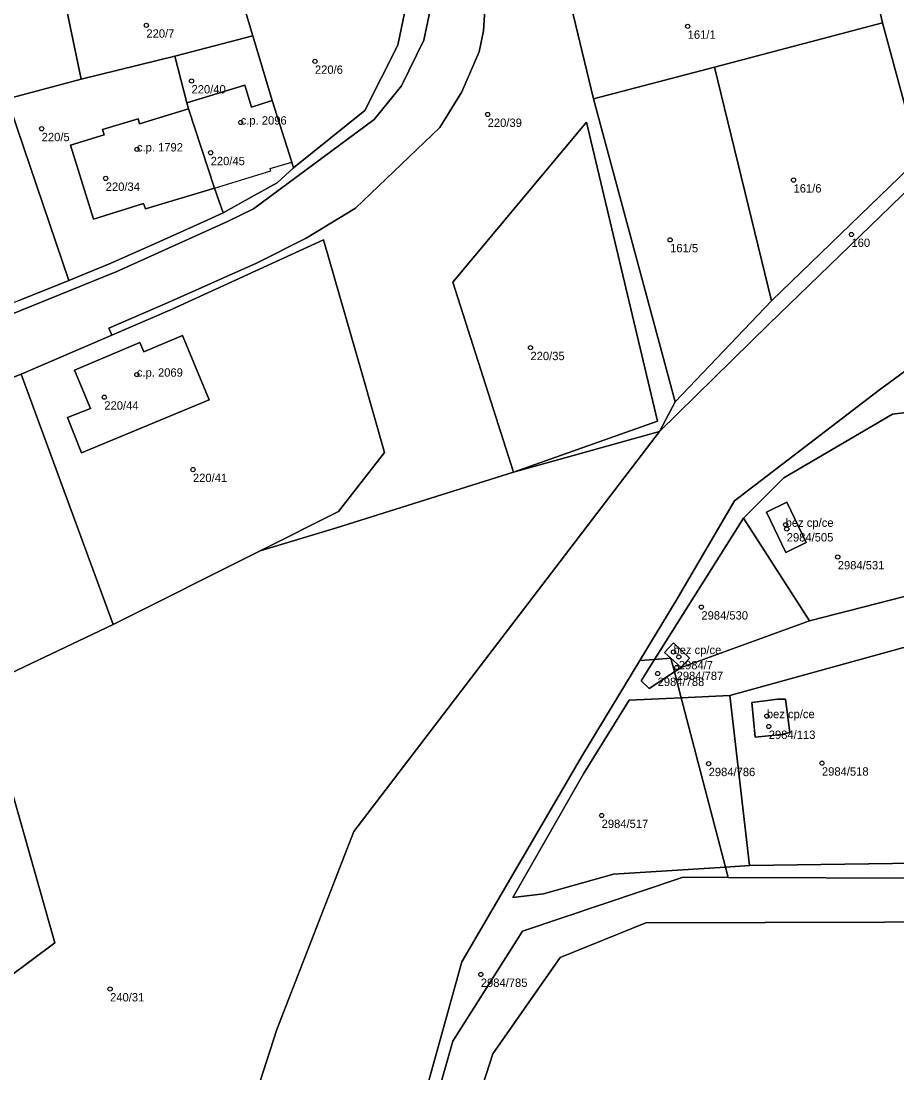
# Model space of a CAD drawing. Extents: x -878211 to -870363, y -1058464 to -1052522.
# Drawn here: x -874079.4 to -873974.6, y -1056112.5 to -1055986.6 of the extents above; entities that cross this region are included whole.
import ezdxf

# ---------------------------------------------------------------- set-up
doc = ezdxf.new("R2010")
doc.units = 0
for name, color, linetype in [('Definiční body', 7, 'Continuous'), ('Polygon budovy', 7, 'Continuous'), ('Polygon parcely', 7, 'Continuous')]:
    doc.layers.add(name, color=color, linetype=linetype)

msp = doc.modelspace()

# ---------------------------------------------------------------- linework, layer by layer
at = {"layer": 'Definiční body'}
for centre in [(-874064.38, -1055987.13994), (-873999.64, -1055987.26994), (-874044.22, -1055991.45994), (-874058.98, -1055993.80994), (-874023.56, -1055997.80994), (-874053.1, -1055998.76994), (-874076.9, -1055999.51994), (-874065.51, -1056001.98994), (-874056.69, -1056002.38994), (-874069.24, -1056005.45994), (-873986.98, -1056005.65994), (-874001.74, -1056012.80994), (-873980.05, -1056012.16994), (-874018.44, -1056025.70994), (-874065.52, -1056028.92994), (-874069.41, -1056031.62994), (-874058.81, -1056040.28994), (-873987.92, -1056046.88994), (-873987.79, -1056047.39994), (-873981.69, -1056050.73994), (-873998, -1056056.73994), (-874001.34, -1056062.10994), (-874000.7, -1056062.68994), (-874003.23, -1056064.68994), (-874000.96, -1056063.96994), (-873990.17, -1056069.77994), (-873989.94, -1056071.01994), (-873997.13, -1056075.46994), (-873983.58, -1056075.40994), (-874009.93, -1056081.66994), (-874024.38, -1056100.67994), (-874068.72, -1056102.41994)]:
    msp.add_circle(centre, 0.25, dxfattribs=at)
at = {"layer": 'Polygon budovy'}
for points in [[(-874052.61, -1055994.31), (-874059.55, -1055996.42), (-874059.34, -1055997.15), (-874056.25, -1056006.62), (-874049.48, -1056004.57), (-874049.57, -1056004.28), (-874046.98, -1056003.51), (-874049.34, -1055996.14), (-874051.81, -1055996.92)], [(-874069.42, -1056000.25), (-874073.45, -1056001.47), (-874070.69, -1056010.33), (-874064.71, -1056008.48), (-874064.5, -1056009.11), (-874056.25, -1056006.62), (-874059.34, -1055997.15), (-874065.19, -1055998.95), (-874065.37, -1055998.34), (-874069.63, -1055999.62)], [(-874073.8, -1056034.07), (-874072.12, -1056038.28), (-874056.85, -1056031.94), (-874060.06, -1056024.27), (-874064.69, -1056026.2), (-874065.16, -1056025.09), (-874072.97, -1056028.39), (-874071.06, -1056032.98)], [(-873990.21, -1056045.38), (-873987.9, -1056050.21), (-873985.45, -1056049.03), (-873987.79, -1056044.18)], [(-874001.33, -1056061.02), (-874002.41, -1056062.16), (-874001.64, -1056062.85), (-874000.43, -1056063.95), (-873999.41, -1056062.83)], [(-873988.84, -1056067.77), (-873991.98, -1056068.16), (-873991.56, -1056072.29), (-873988.36, -1056071.96), (-873987.41, -1056071.73), (-873987.92, -1056067.76)]]:
    msp.add_lwpolyline(points, close=True, dxfattribs=at)
at = {"layer": 'Polygon parcely'}
for points in [[(-873971.94, -1056003.04), (-873966.71, -1056000.36), (-873958.05, -1055994.81), (-873973.04, -1055933.04), (-873973.58, -1055928.96), (-873988.5, -1055932.46), (-873987.49, -1055942.14), (-873979.72, -1055972.17), (-873977.52, -1055981.57), (-873976.33, -1055986.86)], [(-874061.46, -1055955.78), (-874078.43, -1055966.08), (-874076.97, -1055970.76), (-874073.03, -1055969.93), (-874072.64, -1055971.8), (-874066.64, -1055970.52), (-874064.5, -1055980.27), (-874074.5, -1055982.46), (-874072.17, -1055993.59), (-874060.99, -1055990.85), (-874051.65, -1055988.42)], [(-874032.66, -1055981.61), (-874033.78, -1055973.82), (-874038.62, -1055964.71), (-874061.46, -1055955.78), (-874051.65, -1055988.42), (-874049.34, -1055996.14), (-874046.98, -1056003.51), (-874046.78, -1056004.18), (-874038.26, -1055997.34), (-874034.3, -1055989.51)], [(-874095.92, -1055972.47), (-874104.9, -1055975.23), (-874098.11, -1056000.54), (-874081, -1055995.96), (-874072.17, -1055993.59), (-874074.5, -1055982.46), (-874084.39, -1055984.6), (-874086.47, -1055974.86), (-874080.27, -1055973.53), (-874080.69, -1055971.59), (-874076.97, -1055970.76), (-874078.43, -1055966.08), (-874089.47, -1055971)], [(-874009.03, -1055966.11), (-874018.21, -1055965.65), (-874010.89, -1055995.93), (-873996.44, -1055992.14), (-873976.33, -1055986.86), (-873977.52, -1055981.57), (-873983.85, -1055983.05), (-873984.61, -1055984.28), (-873986.14, -1055984.64), (-873987.49, -1055983.84), (-873987.84, -1055982.3), (-873987.07, -1055981.06), (-873988.65, -1055974.24), (-874005.5, -1055979.01)], [(-873971.94, -1056003.04), (-873976.33, -1055986.86), (-873996.44, -1055992.14), (-873989.6, -1056020.11)], [(-874059.55, -1055996.42), (-874052.61, -1055994.31), (-874051.81, -1055996.92), (-874049.34, -1055996.14), (-874051.65, -1055988.42), (-874060.99, -1055990.85)], [(-874070.69, -1056010.33), (-874073.45, -1056001.47), (-874069.42, -1056000.25), (-874069.63, -1055999.62), (-874065.37, -1055998.34), (-874065.19, -1055998.95), (-874059.34, -1055997.15), (-874059.55, -1055996.42), (-874060.99, -1055990.85), (-874072.17, -1055993.59), (-874081, -1055995.96), (-874079.82, -1055999.45), (-874073.66, -1056017.67), (-874068.71, -1056015.62), (-874063.13, -1056013.18), (-874057.09, -1056010.44), (-874055.18, -1056009.57), (-874056.25, -1056006.62), (-874064.5, -1056009.11), (-874064.71, -1056008.48)], [(-873996.44, -1055992.14), (-874010.89, -1055995.93), (-874001.15, -1056032.18), (-873989.6, -1056020.11)], [(-874046.78, -1056004.18), (-874046.98, -1056003.51), (-874049.34, -1055996.14), (-874051.81, -1055996.92), (-874052.61, -1055994.31), (-874059.55, -1055996.42), (-874059.34, -1055997.15), (-874056.25, -1056006.62), (-874055.18, -1056009.57), (-874051.48, -1056007.49), (-874048.75, -1056006)], [(-874079.82, -1055999.45), (-874081, -1055995.96), (-874098.11, -1056000.54), (-874104.71, -1056002.08), (-874096.92, -1056026.27), (-874079.52, -1056020.04), (-874073.66, -1056017.67)], [(-874059.34, -1055997.15), (-874065.19, -1055998.95), (-874065.37, -1055998.34), (-874069.63, -1055999.62), (-874069.42, -1056000.25), (-874073.45, -1056001.47), (-874070.69, -1056010.33), (-874064.71, -1056008.48), (-874064.5, -1056009.11), (-874056.25, -1056006.62)], [(-874003.26, -1056034.48), (-874011.74, -1055998.72), (-874027.74, -1056017.87), (-874020.49, -1056040.6)], [(-874003.26, -1056034.48), (-874020.49, -1056040.6), (-874027.74, -1056017.87), (-874011.74, -1055998.72)], [(-873975.38, -1056008.83), (-873966.71, -1056000.36), (-873971.94, -1056003.04), (-873989.6, -1056020.11), (-874001.15, -1056032.18), (-874003.01, -1056035.73), (-873989.92, -1056022.91)], [(-874068.51, -1056024.22), (-874079.34, -1056028.88), (-874068.35, -1056058.84), (-874050.77, -1056050.02), (-874041.39, -1056045.32), (-874035.88, -1056038.23), (-874038.62, -1056028.71), (-874043.19, -1056012.81), (-874061.28, -1056021.1)], [(-874064.69, -1056026.2), (-874065.16, -1056025.09), (-874072.97, -1056028.39), (-874071.06, -1056032.98), (-874073.8, -1056034.07), (-874072.12, -1056038.28), (-874056.85, -1056031.94), (-874060.06, -1056024.27)], [(-874064.69, -1056026.2), (-874060.06, -1056024.27), (-874056.85, -1056031.94), (-874072.12, -1056038.28), (-874073.8, -1056034.07), (-874071.06, -1056032.98), (-874072.97, -1056028.39), (-874065.16, -1056025.09)], [(-874101.01, -1056036.26), (-874089.71, -1056068.99), (-874083.99, -1056066.24), (-874068.35, -1056058.84), (-874079.34, -1056028.88), (-874082.74, -1056030.19), (-874093.51, -1056033.97)], [(-873985.07, -1056058.37), (-873967.5, -1056053.87), (-873971.22, -1056033.18), (-873975.13, -1056033.66), (-873988.15, -1056041.27), (-873992.97, -1056046.1)], [(-874083.99, -1056066.24), (-874080.7, -1056077.88), (-874075.33, -1056096.89), (-874092.05, -1056109.34), (-874118.47, -1056117.14), (-874116.81, -1056122.76), (-874101.89, -1056134.11), (-874098.83, -1056136.48), (-874062.01, -1056135.86), (-874057.99, -1056135.83), (-874048.77, -1056107.25), (-874039.57, -1056083.57), (-874003.01, -1056035.73), (-874020.49, -1056040.6), (-874041.66, -1056047.24), (-874050.77, -1056050.02), (-874068.35, -1056058.84)], [(-873987.79, -1056044.18), (-873990.21, -1056045.38), (-873987.9, -1056050.21), (-873985.45, -1056049.03)], [(-873987.79, -1056044.18), (-873985.45, -1056049.03), (-873987.9, -1056050.21), (-873990.21, -1056045.38)], [(-874003.6, -1056063), (-874001.64, -1056062.85), (-874002.41, -1056062.16), (-874001.33, -1056061.02), (-873999.41, -1056062.83), (-874000.43, -1056063.95), (-873985.07, -1056058.37), (-873992.97, -1056046.1)], [(-873999.41, -1056062.83), (-874001.33, -1056061.02), (-874002.41, -1056062.16), (-874001.64, -1056062.85), (-874000.43, -1056063.95)], [(-873992.23, -1056087.66), (-873966.56, -1056087.27), (-873968.55, -1056073.84), (-873970.91, -1056060.77), (-873994.59, -1056067.33)], [(-874012.08, -1056076.67), (-874006.62, -1056067.86), (-874000.4, -1056067.59), (-874001.22, -1056064.47), (-874004.25, -1056066.47), (-874005.21, -1056065.57), (-874003.6, -1056063), (-874005.36, -1056063.14), (-874012.21, -1056074.45), (-874026.65, -1056099.18), (-874033.12, -1056122.42), (-874035.94, -1056133.05), (-874034.52, -1056132.5), (-874027.71, -1056108.65), (-874019.41, -1056095.51), (-874000.16, -1056089.06), (-873994.8, -1056089.08), (-873995.12, -1056087.84), (-874008.5, -1056088.69), (-874016.88, -1056091.03), (-874020.55, -1056091.49)], [(-874001.22, -1056064.47), (-874001.64, -1056062.85), (-874003.6, -1056063), (-874005.21, -1056065.57), (-874004.25, -1056066.47)], [(-874001.22, -1056064.47), (-874000.43, -1056063.95), (-874001.64, -1056062.85)], [(-874000.4, -1056067.59), (-874006.62, -1056067.86), (-874012.08, -1056076.67), (-874020.55, -1056091.49), (-874016.88, -1056091.03), (-874008.5, -1056088.69), (-873995.12, -1056087.84)], [(-873992.23, -1056087.66), (-873994.59, -1056067.33), (-874000.4, -1056067.59), (-873995.12, -1056087.84)], [(-873988.36, -1056071.96), (-873987.41, -1056071.73), (-873987.92, -1056067.76), (-873988.84, -1056067.77), (-873991.98, -1056068.16), (-873991.56, -1056072.29)], [(-873988.36, -1056071.96), (-873991.56, -1056072.29), (-873991.98, -1056068.16), (-873988.84, -1056067.77), (-873987.92, -1056067.76), (-873987.41, -1056071.73)], [(-873994.8, -1056089.08), (-873878.08, -1056089.5), (-873840.34, -1056089.55), (-873842.5, -1056082.5), (-873863.42, -1056084.29), (-873881.47, -1056084.35), (-873904.02, -1056084.6), (-873904.11, -1056084.01), (-873924.77, -1056085.52), (-873949.6, -1056086.44), (-873966.56, -1056087.27), (-873992.23, -1056087.66), (-873995.12, -1056087.84)], [(-873965.35, -1056164.18), (-873947.09, -1056155), (-873961.82, -1056094.39), (-874004.66, -1056094.51), (-874014.9, -1056098.66), (-874022.95, -1056110.18), (-874027.4, -1056124.02), (-874040.47, -1056163.31), (-874041.38, -1056163.05), (-874042.62, -1056175.62), (-874041.72, -1056201.74), (-874038.77, -1056221.03), (-874035.3, -1056231.92), (-874016.67, -1056231.12), (-873971.13, -1056232.61), (-873962.33, -1056230.05)]]:
    msp.add_lwpolyline(points, close=True, dxfattribs=at)
for points in [[(-874082.74, -1056030.19), (-874079.34, -1056028.88), (-874068.51, -1056024.22), (-874068.87, -1056023.39), (-874061.78, -1056020.31), (-874051.21, -1056015.58), (-874045.28, -1056012.6), (-874039.36, -1056009.01), (-874029.28, -1055999.36), (-874026.64, -1055995.1), (-874024.59, -1055990.32), (-874024.07, -1055987.79), (-874023.46, -1055978.22), (-874024.41, -1055972.01), (-874026.04, -1055967.55), (-874027.4, -1055965.3), (-874028.36, -1055963.96), (-874031.92, -1055959.69), (-874036.44, -1055955.98), (-874044.57, -1055950.98), (-874047.99, -1055949.47), (-874050.57, -1055948.5), (-874079.9, -1055941.21)], [(-874086.33, -1056024.06), (-874067.92, -1056016.59), (-874054.77, -1056010.67), (-874051.56, -1056009.11), (-874037.13, -1055998.43), (-874033.88, -1055994.4), (-874031.19, -1055988.93), (-874029.78, -1055982.07), (-874030.25, -1055974.01), (-874031.69, -1055968.99), (-874036.22, -1055963.17), (-874039.26, -1055960.99), (-874053.99, -1055954.45), (-874058.59, -1055953.79), (-874062.33, -1055954.49), (-874091.53, -1055969.3)], [(-874091.53, -1055969.3), (-874062.33, -1055954.49), (-874058.59, -1055953.79), (-874053.99, -1055954.45), (-874039.26, -1055960.99), (-874036.22, -1055963.17), (-874031.69, -1055968.99), (-874030.25, -1055974.01), (-874029.78, -1055982.07), (-874031.19, -1055988.93), (-874033.88, -1055994.4), (-874037.13, -1055998.43), (-874051.56, -1056009.11), (-874054.77, -1056010.67), (-874067.92, -1056016.59), (-874086.33, -1056024.06)], [(-873865.37, -1055954.75), (-873878.23, -1055960.39), (-873892.52, -1055966.18), (-873911.31, -1055974.31), (-873925.46, -1055980.46), (-873932.28, -1055983.42), (-873939.2, -1055986.41), (-873946.14, -1055989.65), (-873958.05, -1055994.81), (-873966.71, -1056000.36), (-873975.38, -1056008.83), (-873989.92, -1056022.91), (-874003.01, -1056035.73), (-874039.57, -1056083.57), (-874048.77, -1056107.25), (-874057.99, -1056135.83)], [(-874089.47, -1055971), (-874078.43, -1055966.08), (-874061.46, -1055955.78), (-874038.62, -1055964.71), (-874033.78, -1055973.82), (-874032.66, -1055981.61), (-874034.3, -1055989.51), (-874038.26, -1055997.34), (-874046.78, -1056004.18), (-874048.75, -1056006), (-874051.48, -1056007.49), (-874055.18, -1056009.57), (-874057.09, -1056010.44), (-874063.13, -1056013.18), (-874068.71, -1056015.62), (-874073.66, -1056017.67), (-874079.52, -1056020.04)], [(-874033.12, -1056122.42), (-874026.65, -1056099.18), (-874012.21, -1056074.45), (-874005.36, -1056063.14), (-874001, -1056055.93), (-873994.02, -1056044.02), (-873976.69, -1056030.75), (-873965.62, -1056022.6), (-873960.85, -1056019.45), (-873933.34, -1056004.26), (-873896.15, -1055987.86), (-873830.39, -1055958.21)], [(-874023.46, -1055978.22), (-874024.07, -1055987.79), (-874024.59, -1055990.32), (-874026.64, -1055995.1), (-874029.28, -1055999.36), (-874039.36, -1056009.01), (-874045.28, -1056012.6), (-874051.21, -1056015.58), (-874061.78, -1056020.31), (-874068.87, -1056023.39), (-874068.51, -1056024.22), (-874061.28, -1056021.1), (-874043.19, -1056012.81), (-874038.62, -1056028.71), (-874035.88, -1056038.23), (-874041.39, -1056045.32), (-874050.77, -1056050.02), (-874041.66, -1056047.24), (-874020.49, -1056040.6), (-874003.01, -1056035.73), (-874001.15, -1056032.18), (-874010.89, -1055995.93), (-874018.21, -1055965.65)], [(-873965.62, -1056022.6), (-873976.69, -1056030.75), (-873994.02, -1056044.02), (-874001, -1056055.93), (-874005.36, -1056063.14), (-874003.6, -1056063), (-873992.97, -1056046.1), (-873988.15, -1056041.27), (-873975.13, -1056033.66), (-873971.22, -1056033.18)], [(-873967.5, -1056053.87), (-873985.07, -1056058.37), (-874000.43, -1056063.95), (-874001.22, -1056064.47), (-874000.4, -1056067.59), (-873994.59, -1056067.33), (-873970.91, -1056060.77)], [(-874118.47, -1056117.14), (-874092.05, -1056109.34), (-874075.33, -1056096.89), (-874080.7, -1056077.88), (-874083.99, -1056066.24), (-874089.71, -1056068.99), (-874091.71, -1056069.91), (-874108.7, -1056077.73), (-874128.02, -1056084.85), (-874142.98, -1056090.4), (-874146.75, -1056091.8), (-874167.24, -1056095.36), (-874209.15, -1056102.64), (-874215.93, -1056103.82), (-874220.34, -1056110.44), (-874220.26, -1056114.81)], [(-873840.34, -1056089.55), (-873878.08, -1056089.5), (-873994.8, -1056089.08), (-874000.16, -1056089.06), (-874019.41, -1056095.51), (-874027.71, -1056108.65), (-874034.52, -1056132.5), (-874040.39, -1056153.05), (-874041.38, -1056163.05), (-874040.47, -1056163.31), (-874027.4, -1056124.02), (-874022.95, -1056110.18), (-874014.9, -1056098.66), (-874004.66, -1056094.51), (-873961.82, -1056094.39), (-873878.1, -1056095.5), (-873849.14, -1056094.93)]]:
    msp.add_lwpolyline(points, dxfattribs=at)

# ---------------------------------------------------------------- texts
at = {"layer": 'Definiční body'}
for s, p in [('220/7', (-874064.38, -1055988.629)), ('161/1', (-873999.64, -1055988.759)), ('220/6', (-874044.22, -1055992.949)), ('220/40', (-874058.98, -1055995.299)), ('c.p. 2096', (-874053.1, -1055999.02)), ('220/39', (-874023.56, -1055999.299)), ('220/5', (-874076.9, -1056001.009)), ('c.p. 1792', (-874065.51, -1056002.24)), ('220/45', (-874056.69, -1056003.879)), ('220/34', (-874069.24, -1056006.949)), ('161/6', (-873986.98, -1056007.149)), ('160', (-873980.05, -1056013.659)), ('161/5', (-874001.74, -1056014.299)), ('220/35', (-874018.44, -1056027.199)), ('c.p. 2069', (-874065.52, -1056029.179)), ('220/44', (-874069.41, -1056033.119)), ('220/41', (-874058.81, -1056041.779)), ('bez cp/ce', (-873987.92, -1056047.139)), ('2984/505', (-873987.79, -1056048.889)), ('2984/531', (-873981.69, -1056052.229)), ('2984/530', (-873998, -1056058.229)), ('bez cp/ce', (-874001.34, -1056062.36)), ('2984/7', (-874000.7, -1056064.179)), ('2984/787', (-874000.96, -1056065.459)), ('2984/788', (-874003.23, -1056066.179)), ('bez cp/ce', (-873990.17, -1056070.03)), ('2984/113', (-873989.94, -1056072.509)), ('2984/786', (-873997.13, -1056076.959)), ('2984/518', (-873983.58, -1056076.899)), ('2984/517', (-874009.93, -1056083.159)), ('2984/785', (-874024.38, -1056102.169)), ('240/31', (-874068.72, -1056103.909))]:
    msp.add_text(s, height=0.999996, dxfattribs=at).set_placement(p)

doc.saveas('drawing.dxf')
